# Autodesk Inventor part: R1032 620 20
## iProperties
Created: 2004-10
Part Number: R1032 620 20
Material: 3.2315.71 AlMgSi1 F28
Document SubType Name: Modellieren
Designer: Mittelmeyer Tjeerd
Manufacturer: Standard
Standards Organization: Custom
Description: Tandem-Linear-Set mit Superkugelbüchse einstellbar
Vendor: STAR
Author: Mittelmeyer Tjeerd
Comments: STAR
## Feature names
1. Extrusion2
2. Fase1 [Chamfer]
3. Bohrung1 [Hole]
4. Bohrung2 [Hole]
5. Bohrung3 [Hole]
6. Bohrung4 [Hole]
7. Rechteckige Anordnung1 [Rectangular Pattern]
8. Spiegeln1 [Mirror]
